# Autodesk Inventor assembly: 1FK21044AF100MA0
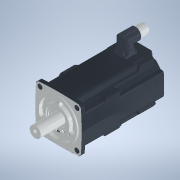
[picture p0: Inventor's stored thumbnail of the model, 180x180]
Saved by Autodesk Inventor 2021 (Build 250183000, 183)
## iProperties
Category: PARTsolutions
Created: 2026-06
Part Number: 1FK21044AF100MA0
Catalog Web Link: www.3dfindit.com
Description: 1FK21044AF100MA0-Servo synchronous motor
Document SubType Name: Assembly
Designer: psAdmin
Mass: 801.95 g
Surface Area: 1112.42 cm^2
Volume: 801.95 cm^3
Density: 1 g/cm^3
Title: 1FK21044AF100MA0
Author: Cadenas PARTsolutions
Comments: Servo synchronous motor
PSOL_IDENT_0: {$CADENAS_DATA/23d-libs/siemens_ag/_cat_/ec/e4/1fk21044af100ma0.prj},193 {STYP=ASS},{VTYP=3D},{NB=1F
PSOL_IDENT_1: K21044AF100MA0},{LINA=1FK21044AF100MA0},{NN=1FK21044AF100MA0},{DATE=19.08.2025 14:01:05},{GEOMDATE=3
PSOL_IDENT_2: 0.07.2025 02:01:01},{VERSION=},{LINEID=10},{WBVAR=},{WBNUMERIC=}  {NB=1FK21044AF100MA0},{LINA=1FK210
PSOL_IDENT_3: 44AF100MA0},{KT=DUMMY},{PREVIEW=../../../_pool_/cb/72/p_d211_xx_00434j.png},{DESCSHORT=SIMOTICS S-1F
PSOL_IDENT_4: K2 HD, SINAMICS S210 3AC 400V-480V, 1.27 Nm, 3000 rpm},{DESCLONG=SIMOTICS S-1FK2 HD servo motor M0=1
PSOL_IDENT_5: .27 Nm; PN = 0.4 kW at nN=3000 rpm (380-480 V); PN = 0.2 kW at nN=1500 rpm (200-240 V); with holding
PSOL_IDENT_6: brake; degree of protection IP64; cylindrical shaft D19x40mm; absolute encoder 22-bit + 12-bit mult
PSOL_IDENT_7: iturn (encoder AM22DQC); with OCC interface; plug size M17, rotatable; SIMOTICS S-1FK2 servomotorfor
PSOL_IDENT_8: a wide range of uses in industrial environments. SIMOTICS S‑1FK2 servomotors are compact synchronou
PSOL_IDENT_9: s motors with a high dynamic performance that set themselves apart as a result of their high power d
PSOL_IDENT_10: ensity, degree of protection and overload capability. The motors are available in two variants: as H
PSOL_IDENT_11: igh Dynamic variant (highest dynamic performance as a result of the low intrinsic moment of inertia
PSOL_IDENT_12: for applications demanding a high dynamic performance with low moved masses) - and as Compact varian
PSOL_IDENT_13: t (precise and stable closed-loop control for medium up to large moved masses as a result of a mediu
PSOL_IDENT_14: m intrinsic moment of inertia). SIMOTICSS‑1FK2 servomotors fully exploit their strengths in a system
PSOL_IDENT_15: with the SINAMICSS210 frequency converter and simple connection using the one cable connection (OCC
PSOL_IDENT_16: ). Advantages include the short control and positioning times, fast and precise correction of distur
PSOL_IDENT_17: bing quantities as well as stable control with a high dynamic performance. The servo motors can be c
PSOL_IDENT_18: onfigured to address a wide range of requirements. For example with and without holding brake, IP64
PSOL_IDENT_19: or IP65 degree of protection, singleturn or multiturn absolute encoders - to name just a few. Furthe
PSOL_IDENT_20: r, the servomotors are available in different shaft heights extending from 20 to 100. A shaft sealin
PSOL_IDENT_21: g ring is available to achieve an IP65 degree of protection and for subsequent mounting at the motor
PSOL_IDENT_22: or as spare part. SIMOTICS - the optimum motor for each and every motion control application.},{INT
PSOL_IDENT_23: NO=195125043275},{SUPPLIERALTNO=1FK2104-4AF10-0MA0},{MANUID=1FK21044AF100MA0},{MANUNAME=Siemens},{MA
PSOL_IDENT_24: NUTYPEDESC=Synchronous motor 1FK2-HD 1.27 NM},{AAU732=SIMOTICS},{AAO057=S-1FK2},{AAU734=SIMOTICS S-1
PSOL_IDENT_25: FK2 HD servo motor M0=1.27 Nm; PN = 0.4 kW at nN=3000 rpm (380-480 V); PN = 0.2 kW at nN=1500 rpm (2
PSOL_IDENT_26: 00-240 V); with holding brake; degree of protection IP64; cylindrical shaft D19x40mm; absolute encod
PSOL_IDENT_27: er 22-bit + 12-bit multiturn (encoder AM22DQC); with OCC interface; plug size M17, rotatable;},{AAW3
PSOL_IDENT_28: 38=Synchronous motor 1FK2-HD 1.27 NM},{AAO742=SIMOTICS},{AAO663=4042948694015},{NOCUPEROU=1},{PRICEQ
PSOL_IDENT_29: UANTITY=1},{QUANTITYMIN=1},{QUANTITYINT=1},{CTN=85015100},{COO=DE},{AAO676=1FK2104-4AF10-0MA0},{AAO6
PSOL_IDENT_30: 77=Siemens AG},{ORDERUNIT=C62},{CONTENTUNIT=C62}
NB: 1FK21044AF100MA0
NN: 1FK21044AF100MA0
NT: Servo synchronous motor
NBSYN: $MANUID.
LINA: 1FK21044AF100MA0
CATALOG: SIEMENS
PREVIEW: ../../../_pool_/cb/72/p_d211_xx_00434j.png
DESCSHORT: SIMOTICS S-1FK2 HD, SINAMICS S210 3AC 400V-480V, 1.27 Nm, 3000 rpm
DESCLONG: SIMOTICS S-1FK2 HD servo motor M0=1.27 Nm; PN = 0.4 kW at nN=3000 rpm (380-480 V); PN = 0.2 kW at nN=1500 rpm (200-240 V); with holding brake; degree of protect
INTNO: 195125043275
SUPPLIERALTNO: 1FK2104-4AF10-0MA0
MANUID: 1FK21044AF100MA0
MANUNAME: Siemens
MANUTYPEDESC: Synchronous motor 1FK2-HD 1.27 NM
AAU732: SIMOTICS
AAO057: S-1FK2
AAU734: SIMOTICS S-1FK2 HD servo motor M0=1.27 Nm; PN = 0.4 kW at nN=3000 rpm (380-480 V); PN = 0.2 kW at nN=1500 rpm (200-240 V); with holding brake; degree of protect
AAW338: Synchronous motor 1FK2-HD 1.27 NM
AAO742: SIMOTICS
AAO663: 4042948694015.0
NOCUPEROU: 1
PRICEQUANTITY: 1
QUANTITYMIN: 1
QUANTITYINT: 1
CTN: 85015100
COO: DE
ARTICLENO: 1FK21044AF100MA0
BOMINFO: 1FK21044AF100MA0
CREATOR: CADENAS GmbH
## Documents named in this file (24)
- e:\temp\worker_COMMON_23\temp\tmp_3608_4_gBtVX\format_0\1FK21044AF100MA0.iam
- e:\temp\worker_COMMON_23\temp\tmp_3608_4_gBtVX\format_0\1FK21044AF100MA0_PART1.ipt
- e:\temp\worker_COMMON_23\temp\tmp_3608_4_gBtVX\format_0\1FK21044AF100MA0_PART2.ipt
- e:\temp\worker_COMMON_23\temp\tmp_3608_4_gBtVX\format_0\1FK21044AF100MA0_PART3.ipt
- e:\temp\worker_COMMON_23\temp\tmp_3608_4_gBtVX\format_0\1FK21044AF100MA0_PART4.ipt
- e:\temp\worker_COMMON_23\temp\tmp_3608_4_gBtVX\format_0\1FK21044AF100MA0_PART5.ipt
- e:\temp\worker_COMMON_23\temp\tmp_3608_4_gBtVX\format_0\1FK21044AF100MA0_PART6.ipt
- e:\temp\worker_COMMON_23\temp\tmp_3608_4_gBtVX\format_0\1FK21044AF100MA0_PART7.ipt
- e:\temp\worker_COMMON_23\temp\tmp_3608_4_gBtVX\format_0\1FK21044AF100MA0_PART8.ipt
- e:\temp\worker_COMMON_23\temp\tmp_3608_4_gBtVX\format_0\1FK21044AF100MA0_PART9.ipt
- e:\temp\worker_COMMON_23\temp\tmp_3608_4_gBtVX\format_0\1FK21044AF100MA0_PART10.ipt
- e:\temp\worker_COMMON_23\temp\tmp_3608_4_gBtVX\format_0\1FK21044AF100MA0_PART11.ipt
- e:\temp\worker_COMMON_23\temp\tmp_3608_4_gBtVX\format_0\1FK21044AF100MA0_PART12.ipt
- e:\temp\worker_COMMON_23\temp\tmp_3608_4_gBtVX\format_0\1FK21044AF100MA0_PART13.ipt
- e:\temp\worker_COMMON_23\temp\tmp_3608_4_gBtVX\format_0\1FK21044AF100MA0_PART14.ipt
- e:\temp\worker_COMMON_23\temp\tmp_3608_4_gBtVX\format_0\1FK21044AF100MA0_PART15.ipt
- e:\temp\worker_COMMON_23\temp\tmp_3608_4_gBtVX\format_0\1FK21044AF100MA0_PART16.ipt
- e:\temp\worker_COMMON_23\temp\tmp_3608_4_gBtVX\format_0\1FK21044AF100MA0_PART17.ipt
- e:\temp\worker_COMMON_23\temp\tmp_3608_4_gBtVX\format_0\1FK21044AF100MA0_PART18.ipt
- e:\temp\worker_COMMON_23\temp\tmp_3608_4_gBtVX\format_0\1FK21044AF100MA0_PART19.ipt
- e:\temp\worker_COMMON_23\temp\tmp_3608_4_gBtVX\format_0\1FK21044AF100MA0_PART20.ipt
- e:\temp\worker_COMMON_23\temp\tmp_3608_4_gBtVX\format_0\1FK21044AF100MA0_PART21.ipt
- e:\temp\worker_COMMON_23\temp\tmp_3608_4_gBtVX\format_0\1FK21044AF100MA0_PART22.ipt
- e:\temp\worker_COMMON_23\temp\tmp_3608_4_gBtVX\format_0\1FK21044AF100MA0_PART23.ipt
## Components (23 placed, 23 different names)
1. 1FK21044AF100MA0_PART1:1
2. 1FK21044AF100MA0_PART2:1
3. 1FK21044AF100MA0_PART3:1
4. 1FK21044AF100MA0_PART4:1
5. 1FK21044AF100MA0_PART5:1
6. 1FK21044AF100MA0_PART6:1
7. 1FK21044AF100MA0_PART7:1
8. 1FK21044AF100MA0_PART8:1
9. 1FK21044AF100MA0_PART9:1
10. 1FK21044AF100MA0_PART10:1
11. 1FK21044AF100MA0_PART11:1
12. 1FK21044AF100MA0_PART12:1
13. 1FK21044AF100MA0_PART13:1
14. 1FK21044AF100MA0_PART14:1
15. 1FK21044AF100MA0_PART15:1
16. 1FK21044AF100MA0_PART16:1
17. 1FK21044AF100MA0_PART17:1
18. 1FK21044AF100MA0_PART18:1
19. 1FK21044AF100MA0_PART19:1
20. 1FK21044AF100MA0_PART20:1
21. 1FK21044AF100MA0_PART21:1
22. 1FK21044AF100MA0_PART22:1
23. 1FK21044AF100MA0_PART23:1
